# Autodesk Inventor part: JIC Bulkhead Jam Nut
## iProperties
Category: Hydraulics
Title: JIC Bulkhead Jam Nut
Author: QBZ
Shininess: 27.0
PropertySet Name: _Private Model Information
Created: 2001-03
Part Number: 210212-8S
Description: Bulkhead Jam Nut -8
Document SubType Name: Modeling
Designer: QBZ
Material: Steel, Mild
Catalog Web Link: http://www.aeroquip.com
Control State: 0
Master: False
Checked Out: False
PropertySet Name: Design Tracking Control
Density: 7.860000000000001
Volumn: 2.138618301835608
Area: 16.833572068141628
PropertySet Name: Model Information
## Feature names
1. Extrusion1
2. Revolution1
